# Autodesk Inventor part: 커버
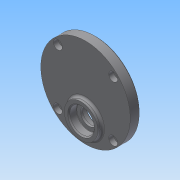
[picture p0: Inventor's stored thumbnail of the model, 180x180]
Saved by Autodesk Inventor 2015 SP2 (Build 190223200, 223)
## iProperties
Created: 2015-06
Part Number: 커버
Material: 일반
Document SubType Name: Modeling
Designer: AMC
Density: 1 g/cm^3
Appearance: 기본값
Author: AMC
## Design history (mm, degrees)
sketch "스케치1"
  geometry: C1 r 40 at (0, 0); 1 further point
  constraints: 1 centre point, 1 coincident
  dimensions: "d0" = 80 diameter of C1
extrude "돌출1" new body sketch "스케치1" distance "d1" = 9; taper "d2" = 0 deg
sketch "스케치2"
  geometry: C1 r 15 at (0, -20); 1 further point
  constraints: 1 centre point, 1 vertical alignment
  dimensions: "d3" = 30 diameter of C1; "d4" = 20 distance of point (0, 0) C1.centre
extrude "돌출2" join sketch "스케치2" distance "d5" = 4; taper "d6" = 0 deg
sketch "스케치3"
  geometry: C1 r 14 at (0, 20); C2 r 14 at (0, -11); 1 further point
  constraints: 2 centre point, 2 vertical alignment
  dimensions: "d7" = 28 diameter of C1; "d8" = 20 distance of C1.centre point (0, 0); "d9" = 28 diameter of C2; "d10" = 11 distance of point (0, 0) C2.centre
extrude "돌출3" join sketch "스케치3" distance "d11" = 3; taper "d12" = 0 deg
hole "구멍1" diameter "d15" = 15; stored, may be unused: countersink angle "d19" = 90 deg, drill point angle "d21" = 118 deg; dims "d13" = 10, "d14" = 10, "d16" = 6, "d17" = 22, "d18" = 7, "d20" = 8
hole "구멍2" diameter "d24" = 22; stored, may be unused: countersink angle "d28" = 90 deg, drill point angle "d30" = 0 deg; dims "d22" = 10, "d23" = 10, "d25" = 6, "d26" = 22, "d27" = 7, "d29" = 7
fillet "모깎기1" dims "d31" = 0.3
fillet "모깎기2" dims "d32" = 2
chamfer "모따기1" distance "d33" = 1; stored, may be unused: second distance "d34" = 2, angle "d35" = 45 deg
hole "구멍3" diameter "d38" = 18; stored, may be unused: countersink angle "d42" = 90 deg, drill point angle "d44" = 0 deg; dims "d36" = 10, "d37" = 10, "d39" = 6, "d40" = 22, "d41" = 7, "d43" = 8
fillet "모깎기3" dims "d45" = 2
fillet "모깎기4" dims "d46" = 0.3
chamfer "모따기2" distance "d47" = 1; stored, may be unused: second distance "d48" = 2, angle "d49" = 45 deg
sketch "스케치4"
  geometry: L1 (0, 0)-(33.785, 33.785); L2 (0, 0)-(30.266, 0); 1 further point
  constraints: 4 end point, 1 horizontal, 1 point on line
  dimensions: "d51" = 45 deg angle of L2 L1; "d53" = 35 distance of L1.start point (24.749, 24.749)
hole "구멍4" sketch "스케치4" at (24.749, 24.749) diameter "d54" = 4.5; stored, may be unused: countersink angle "d58" = 90 deg, drill point angle "d60" = 0 deg; dims "d55" = 6, "d56" = 8, "d57" = 4.4, "d59" = 8
chamfer "모따기3" distance "d64" = 1; stored, may be unused: second distance "d65" = 2, angle "d66" = 45 deg
node "솔리드1"
pattern_circular "원형 패턴1" dims angle "d62" = 360 deg
